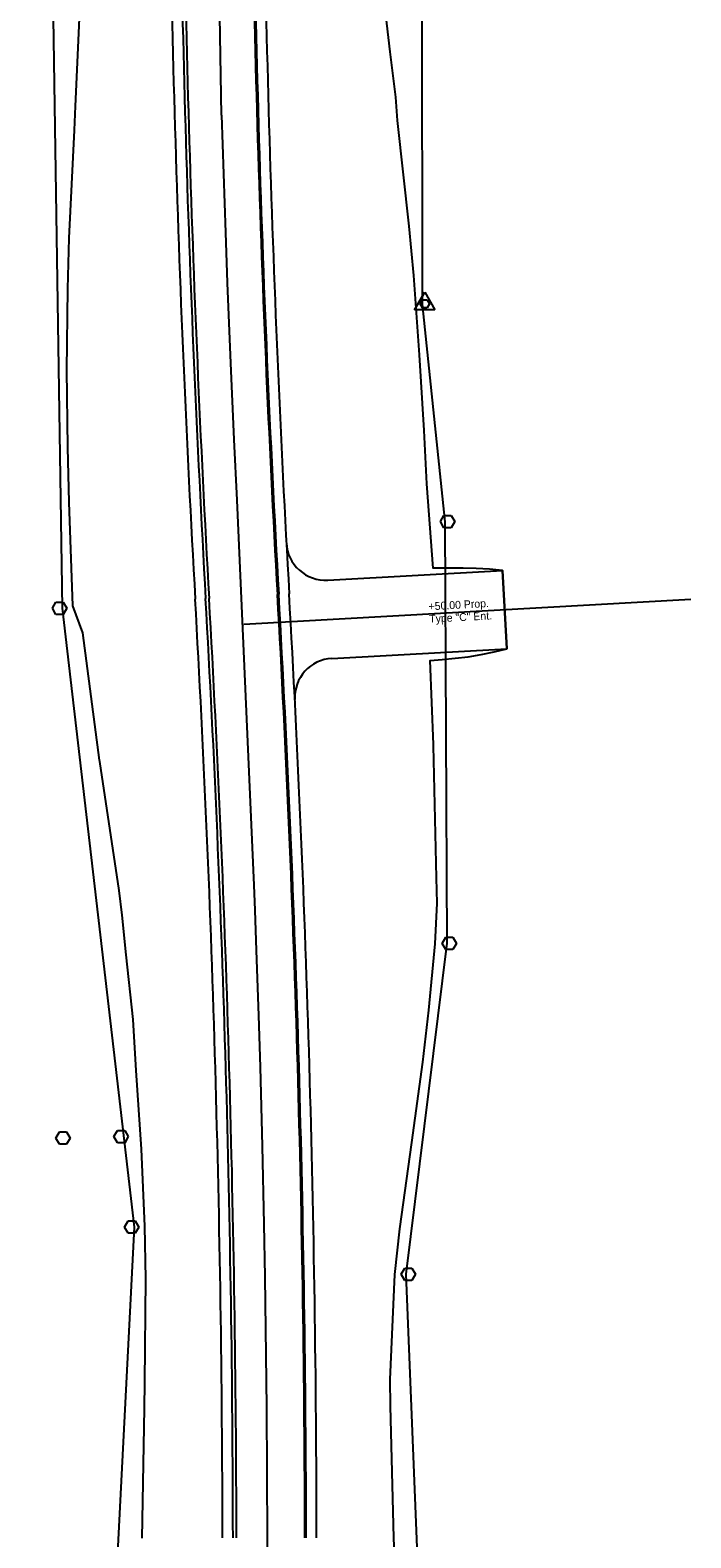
# Model space of a CAD drawing. Extents: x 18436148 to 18440034, y 7649939 to 7652226.
# Drawn here: x 18438242 to 18438495, y 7650505 to 7651082 of the extents above; entities that cross this region are included whole.
import ezdxf

# ---------------------------------------------------------------- set-up
doc = ezdxf.new("R2010")
doc.units = 0
for name, color, linetype in [('ATVEHICLE', 7, 'Continuous'), ('Drainage', 7, 'Continuous'), ('dsnCellsScaleBlock', 7, 'Continuous'), ('EdgePaved', 7, 'Continuous'), ('Seeding', 7, 'Continuous'), ('TC_PCCPavement', 7, 'Continuous'), ('TL_DitchBack', 7, 'Continuous'), ('TL_ShoulderBtm', 7, 'Continuous'), ('TSDETAILS', 7, 'Continuous'), ('TSOUTLINE', 7, 'Continuous')]:
    doc.layers.add(name, color=color, linetype=linetype)

msp = doc.modelspace()

# ---------------------------------------------------------------- linework, layer by layer
at = {"layer": 'ATVEHICLE'}
for centre, radius, start, end in [((18444813.07, 7651234.67), 6514, 180.077652, 183.256258), ((18444813.07, 7651234.67), 6486, 180.077652, 183.256258), ((18431834.06, 7650496.24), 6486, 0.077652, 3.256258), ((18431834.06, 7650496.24), 6514, 0.077652, 3.256258)]:
    msp.add_arc(centre, radius, start, end, dxfattribs=at)
at = {"layer": 'Drainage'}
for p, q in [((18438399.36, 7650894.06), (18438400.74, 7650896.44)), ((18438400.74, 7650891.68), (18438399.36, 7650894.06)), ((18438400.74, 7650896.44), (18438403.49, 7650896.44)), ((18438403.49, 7650891.68), (18438400.74, 7650891.68)), ((18438403.49, 7650896.44), (18438404.86, 7650894.06)), ((18438404.86, 7650894.06), (18438403.49, 7650891.68)), ((18438250.96, 7650860.89), (18438252.34, 7650863.27)), ((18438252.34, 7650863.27), (18438255.09, 7650863.27)), ((18438255.09, 7650863.27), (18438256.46, 7650860.89)), ((18438252.34, 7650858.5), (18438250.96, 7650860.89)), ((18438255.09, 7650858.5), (18438252.34, 7650858.5)), ((18438256.46, 7650860.89), (18438255.09, 7650858.5)), ((18438400.06, 7650732.63), (18438401.43, 7650735.01)), ((18438401.43, 7650730.25), (18438400.06, 7650732.63)), ((18438401.43, 7650735.01), (18438404.18, 7650735.01)), ((18438404.18, 7650730.25), (18438401.43, 7650730.25)), ((18438404.18, 7650735.01), (18438405.56, 7650732.63)), ((18438405.56, 7650732.63), (18438404.18, 7650730.25)), ((18438274.51, 7650658.66), (18438275.88, 7650661.04)), ((18438275.88, 7650661.04), (18438278.63, 7650661.04)), ((18438278.63, 7650661.04), (18438280.01, 7650658.66)), ((18438252.27, 7650658.1), (18438253.64, 7650660.48)), ((18438253.64, 7650655.71), (18438252.27, 7650658.1)), ((18438253.64, 7650660.48), (18438256.39, 7650660.48)), ((18438256.39, 7650655.71), (18438253.64, 7650655.71)), ((18438256.39, 7650660.48), (18438257.77, 7650658.1)), ((18438257.77, 7650658.1), (18438256.39, 7650655.71)), ((18438275.88, 7650656.27), (18438274.51, 7650658.66)), ((18438278.63, 7650656.27), (18438275.88, 7650656.27)), ((18438280.01, 7650658.66), (18438278.63, 7650656.27)), ((18438278.54, 7650624.02), (18438279.92, 7650626.41)), ((18438279.92, 7650626.41), (18438282.67, 7650626.41)), ((18438282.67, 7650626.41), (18438284.04, 7650624.02)), ((18438279.92, 7650621.64), (18438278.54, 7650624.02)), ((18438282.67, 7650621.64), (18438279.92, 7650621.64)), ((18438284.04, 7650624.02), (18438282.67, 7650621.64)), ((18438384.39, 7650605.95), (18438385.76, 7650608.33)), ((18438385.76, 7650603.57), (18438384.39, 7650605.95)), ((18438385.76, 7650608.33), (18438388.51, 7650608.33)), ((18438388.51, 7650603.57), (18438385.76, 7650603.57)), ((18438388.51, 7650608.33), (18438389.89, 7650605.95)), ((18438389.89, 7650605.95), (18438388.51, 7650603.57))]:
    msp.add_line(p, q, dxfattribs=at)
at = {"layer": 'EdgePaved'}
for p, q in [((18438356.27, 7650871.67), (18438423.18, 7650875.37)), ((18438423.18, 7650875.37), (18438424.83, 7650845.41)), ((18438357.87, 7650841.71), (18438424.83, 7650845.41))]:
    msp.add_line(p, q, dxfattribs=at)
for centre, start, end in [((18438355.44, 7650886.64), 183.08487, 273.16281), ((18438358.69, 7650826.73), 93.16281, 182.8997)]:
    msp.add_arc(centre, 15, start, end, dxfattribs=at)
at = {"layer": 'Seeding'}
for p, q in [((18438389.54, 7650975.16), (18438393.41, 7650981.87)), ((18438391.66, 7650977.4), (18438392.54, 7650978.91)), ((18438392.54, 7650978.91), (18438394.29, 7650978.91)), ((18438393.41, 7650981.87), (18438397.29, 7650975.16)), ((18438394.29, 7650978.91), (18438395.16, 7650977.4)), ((18438397.29, 7650975.16), (18438389.54, 7650975.16)), ((18438392.54, 7650975.88), (18438391.66, 7650977.4)), ((18438394.29, 7650975.88), (18438392.54, 7650975.88)), ((18438395.16, 7650977.4), (18438394.29, 7650975.88))]:
    msp.add_line(p, q, dxfattribs=at)
at = {"layer": 'TC_PCCPavement'}
for p, q in [((18438391.39, 7651733.19), (18438392.41, 7650977.35)), ((18438242.47, 7651667.94), (18438254.71, 7650860.95)), ((18438392.41, 7650977.35), (18438401.11, 7650894.01)), ((18438401.11, 7650894.01), (18438401.81, 7650732.69)), ((18438254.71, 7650860.95), (18438282.29, 7650624.06)), ((18438401.81, 7650732.69), (18438386.14, 7650605.99)), ((18438282.29, 7650624.06), (18438269.8, 7650381.63)), ((18438386.14, 7650605.99), (18438395.03, 7650387.67))]:
    msp.add_line(p, q, dxfattribs=at)
at = {"layer": 'TL_DitchBack'}
msp.add_line((18438324.16, 7650854.87), (18438495.17, 7650864.32), dxfattribs=at)
at = {"layer": 'TL_ShoulderBtm'}
msp.add_line((18438315.69, 7651049.68), (18438313.19, 7651197.34), dxfattribs=at)
for points in [[(18438315.69, 7651049.68), (18438317.14, 7651004.7), (18438317.85, 7650985.52), (18438319.1, 7650954.74), (18438320.43, 7650925.47), (18438321.57, 7650902.32)], [(18438321.58, 7650902.32), (18438328.02, 7650754.94), (18438328.39, 7650745.35), (18438328.96, 7650729.96), (18438329.82, 7650704.97), (18438330.42, 7650685.28), (18438331.23, 7650654.99), (18438331.89, 7650625.2), (18438332.26, 7650605), (18438332.8, 7650565.11), (18438332.9, 7650555.01), (18438333.16, 7650505.01), (18438334.2, 7650396.45)]]:
    msp.add_lwpolyline(points, dxfattribs=at)
for centre, radius, start, end in [((18444813.9, 7651234.67), 6513.5, 180.077652, 183.256258), ((18444813.07, 7651234.67), 6486.5, 180.077652, 183.256258), ((18431834.89, 7650496.24), 6486.5, 0.077652, 3.256258), ((18431834.06, 7650496.24), 6513.5, 0.077652, 3.256258)]:
    msp.add_arc(centre, radius, start, end, dxfattribs=at)
at = {"layer": 'TSDETAILS'}
for centre, radius, start, end in [((18444813.07, 7651234.67), 6518, 180.077652, 183.256258), ((18444813.07, 7651234.67), 6482, 180.077652, 183.256258), ((18431834.06, 7650496.24), 6482, 0.077652, 3.256258), ((18431834.06, 7650496.24), 6518, 0.077652, 3.256258)]:
    msp.add_arc(centre, radius, start, end, dxfattribs=at)
at = {"layer": 'TSOUTLINE'}
for points in [[(18438383.65, 7650455.12), (18438381.54, 7650505.12), (18438380.35, 7650555.47), (18438380.15, 7650565.64), (18438381.96, 7650605.86), (18438383.88, 7650623.4), (18438388.42, 7650656.41), (18438392.69, 7650687.11), (18438395.02, 7650707.08), (18438397.41, 7650732.43), (18438398.12, 7650748.03), (18438397.85, 7650757.73), (18438396.78, 7650808.27), (18438396.75, 7650808.77), (18438395.5, 7650840.87), (18438400.02, 7650841.33), (18438405, 7650841.84), (18438409.98, 7650842.35), (18438414.94, 7650843.14), (18438419.89, 7650844.25), (18438424.83, 7650845.41), (18438423.18, 7650875.37), (18438418.14, 7650875.84), (18438413.12, 7650876.1), (18438408.11, 7650876.19), (18438403.1, 7650876.27), (18438398.09, 7650876.3), (18438396.61, 7650876.27), (18438394.19, 7650908.49), (18438393.14, 7650928.94), (18438391.33, 7650957.86), (18438389.17, 7650988.25), (18438387.43, 7651007.19), (18438383, 7651047.54), (18438382.28, 7651056.53), (18438380.19, 7651073.84), (18438376.32, 7651106.9)], [(18438285.26, 7650504.99), (18438286.16, 7650554.62), (18438286.34, 7650564.65), (18438286.74, 7650604.27), (18438286.37, 7650624.32), (18438285.01, 7650653.89), (18438283, 7650683.92), (18438281.91, 7650703.45), (18438279.25, 7650728.18), (18438277.62, 7650743.41), (18438276.52, 7650752.9), (18438269.11, 7650802.2), (18438269.03, 7650802.69), (18438262.57, 7650851.47), (18438258.83, 7650861.77), (18438257.38, 7650901.54), (18438256.89, 7650922.45), (18438256.52, 7650952.04), (18438256.91, 7650983.18), (18438257.42, 7651002.59), (18438259.48, 7651043.94), (18438259.79, 7651053.13), (18438262.05, 7651103.62)]]:
    msp.add_lwpolyline(points, dxfattribs=at)

# ---------------------------------------------------------------- texts
at = {"layer": 'dsnCellsScaleBlock'}
for s, p in [('+50.00 Prop.', (18438394.95, 7650860.11)), ('Type "C" Ent.', (18438395.21, 7650855.32))]:
    msp.add_text(s, height=3, rotation=3.16281, dxfattribs=at).set_placement(p)

doc.saveas('drawing.dxf')
